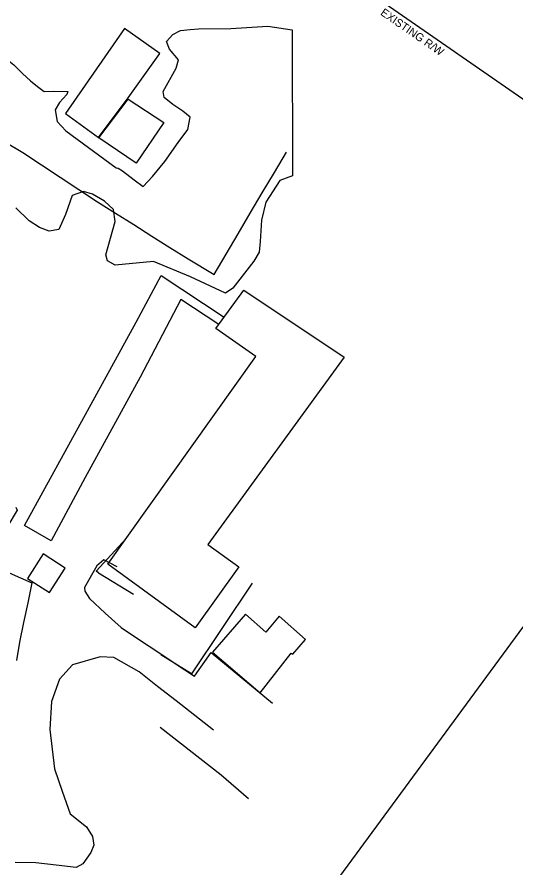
# Model space of a CAD drawing. Extents: x 2262665 to 2270527, y 505476 to 514960.
# Drawn here: x 2266517.9 to 2266717.5, y 511144.5 to 511484.8 of the extents above; entities that cross this region are included whole.
import ezdxf

# ---------------------------------------------------------------- set-up
doc = ezdxf.new("R2010")
doc.units = 0
for name, color, linetype in [('Exist Building', 7, 'Continuous'), ('Exist Building Metal Canopy', 7, 'Continuous'), ('Exist Other Culture Area Outline', 7, 'Continuous'), ('Exist Other Culture Fence Line', 7, 'Continuous'), ('Exist Other Culture Gate', 7, 'Continuous'), ('Exist Right of Way Line', 7, 'Continuous'), ('Exist Right of Way Line Text', 7, 'Continuous'), ('Exist Roads Soil', 7, 'Continuous'), ('Exist Vegetation Woods Line', 7, 'Continuous')]:
    doc.layers.add(name, color=color, linetype=linetype)

msp = doc.modelspace()

# ---------------------------------------------------------------- linework, layer by layer
at = {"layer": 'Exist Building'}
for points in [[(2266560.93, 511480.24), (2266537.28, 511446.18), (2266550.52, 511436.59), (2266562.38, 511452.46), (2266575.02, 511470.27)], [(2266606.61, 511264.93), (2266589.12, 511240.57), (2266554.22, 511265.94), (2266613.42, 511349.02), (2266597.45, 511360.18), (2266608.63, 511375.63), (2266648.76, 511348.83), (2266594.21, 511273.91)], [(2266609.31, 511246), (2266596.17, 511230.78), (2266615.18, 511214.55), (2266627.52, 511230.37), (2266628.22, 511229.93), (2266633.28, 511235.88), (2266622.82, 511245.18), (2266617.42, 511238.76)]]:
    msp.add_lwpolyline(points, close=True, dxfattribs=at)
at = {"layer": 'Exist Building Metal Canopy'}
msp.add_line((2266550.63, 511436.52), (2266562.42, 511452.01), dxfattribs=at)
msp.add_lwpolyline([(2266562.42, 511452.01), (2266576.62, 511442.59), (2266565.56, 511426.37), (2266550.63, 511436.52)], dxfattribs=at)
at = {"layer": 'Exist Other Culture Area Outline'}
msp.add_lwpolyline([(2266598.65, 511361.84), (2266583.47, 511371.86), (2266567.21, 511340.71), (2266545.23, 511300.7), (2266531.57, 511275.36), (2266520.88, 511281.5), (2266546.17, 511327.3), (2266565.58, 511362.73), (2266575.61, 511381.41), (2266600.8, 511364.81)], dxfattribs=at)
msp.add_lwpolyline([(2266537.24, 511264.35), (2266528.41, 511270.06), (2266522.11, 511260.3), (2266530.93, 511254.6)], close=True, dxfattribs=at)
at = {"layer": 'Exist Other Culture Fence Line'}
for points in [[(2266550.58, 511262.55), (2266549.59, 511263.13), (2266561.57, 511276.27)], [(2266550.58, 511262.55), (2266564.52, 511254.02)], [(2266612.03, 511258.39), (2266587.78, 511222.06)], [(2266575.2, 511200.76), (2266599.58, 511181.72), (2266610.52, 511172.23)]]:
    msp.add_lwpolyline(points, dxfattribs=at)
at = {"layer": 'Exist Other Culture Gate'}
msp.add_line((2266587.78, 511222.06), (2266575.51, 511229.67), dxfattribs=at)
at = {"layer": 'Exist Right of Way Line'}
for p in [(2266538.53, 511578.02), (2265436.99, 509495.4)]:
    msp.add_line(p, (2266823.18, 511380.77), dxfattribs=at)
at = {"layer": 'Exist Roads Soil'}
for points in [[(2266477.55, 511455.85), (2266484.74, 511451.58), (2266491.93, 511447.31), (2266499.12, 511443.03), (2266506.31, 511438.76), (2266513.26, 511434.71), (2266520.22, 511430.66), (2266527.69, 511425.73), (2266535.16, 511420.8), (2266542.64, 511415.87), (2266550.11, 511410.95), (2266557.36, 511406.37), (2266564.6, 511401.79), (2266571.85, 511397.21), (2266579.1, 511392.63), (2266586.35, 511388.05), (2266596.72, 511381.85), (2266601.55, 511390.01), (2266606.37, 511398.16), (2266611.2, 511406.32), (2266616.02, 511414.47), (2266620.85, 511422.63), (2266625.68, 511430.78)], [(2266517.5, 511288.72), (2266518.03, 511287.58), (2266513.9, 511280.59)], [(2266557.93, 511264.97), (2266552.59, 511267.69), (2266549.89, 511265.31), (2266544.87, 511256.7), (2266545.06, 511255.15), (2266546.9, 511252.27), (2266553.25, 511246.44), (2266559.61, 511240.6), (2266566.94, 511235.74), (2266574.27, 511230.89), (2266581.6, 511226.03), (2266588.93, 511221.17), (2266595.64, 511230.67), (2266601.76, 511225.59), (2266607.88, 511220.51), (2266614.01, 511215.43), (2266620.13, 511210.35)], [(2266514.75, 511262.54), (2266523.84, 511258.47), (2266522.2, 511250.57), (2266520.57, 511242.67), (2266518.94, 511234.77), (2266517.72, 511227.4)], [(2266596.48, 511199.59), (2266589.05, 511205.42), (2266581.61, 511211.26), (2266574.18, 511217.09), (2266566.74, 511222.93), (2266556.62, 511228.61), (2266551.13, 511228.9), (2266540.17, 511225.77), (2266534.97, 511219.92), (2266531.77, 511211.1), (2266531.09, 511199.9), (2266531.98, 511191.99), (2266532.86, 511184.09), (2266536.05, 511175.13), (2266539.24, 511166.18), (2266545.73, 511160.91), (2266548.06, 511157.02), (2266548.67, 511153.54), (2266547.46, 511150.65), (2266544.22, 511146.12), (2266541.64, 511144.67), (2266533.58, 511145.56), (2266525.52, 511146.46), (2266517.19, 511146.69)]]:
    msp.add_lwpolyline(points, dxfattribs=at)
at = {"layer": 'Exist Vegetation Woods Line'}
for points in [[(2266495.74, 511490.65), (2266496.69, 511484.03), (2266500.48, 511478.79), (2266505.52, 511474.86), (2266510.52, 511470.56), (2266516.59, 511465.71), (2266520.17, 511462.29), (2266523.28, 511459.37), (2266526.14, 511457.07), (2266528.73, 511455.02), (2266532.56, 511455.11), (2266538.27, 511455.1), (2266537.85, 511453.86), (2266534.92, 511450.61), (2266533.14, 511447.7), (2266534.05, 511443.03), (2266537.46, 511439.33), (2266557.64, 511424.56)], [(2266587.22, 511479.81), (2266590.56, 511480.05), (2266603.42, 511480.27), (2266618.3, 511481.19), (2266628, 511479.75), (2266628.12, 511421.24), (2266622.99, 511419.4), (2266617.44, 511410.76), (2266615.71, 511403.57), (2266615.13, 511395.06), (2266614.73, 511390.74), (2266612.66, 511387.18), (2266604.21, 511376.42), (2266601.32, 511374.36), (2266587.34, 511380.93), (2266572.56, 511387.09), (2266557.14, 511385.53), (2266554.09, 511387.3), (2266553.43, 511389.69), (2266557.24, 511403.07), (2266556.56, 511407.79), (2266552.98, 511411.21), (2266548.13, 511413.92), (2266544.48, 511415.02), (2266539.97, 511413.41), (2266537.38, 511405.85), (2266534.64, 511399.87), (2266530.74, 511399.19), (2266526.9, 511400.68), (2266522.8, 511403.32), (2266517.43, 511408.48)], [(2266557.64, 511424.56), (2266558.36, 511424.38), (2266560.12, 511423.33), (2266564.78, 511419.65), (2266568.44, 511417.1), (2266572.13, 511421.1), (2266577.04, 511427.04), (2266582.44, 511434.6), (2266586.25, 511439.79), (2266587.17, 511444.83), (2266584.27, 511447.12), (2266580.23, 511449.79), (2266576.72, 511452.7), (2266576.33, 511455.06), (2266581.52, 511464.4), (2266582.57, 511467.76), (2266578.92, 511471.94), (2266577.67, 511475.07), (2266580.21, 511477.85), (2266583.38, 511479.4), (2266587.22, 511479.81)]]:
    msp.add_lwpolyline(points, dxfattribs=at)

# ---------------------------------------------------------------- texts
at = {"layer": 'Exist Right of Way Line Text'}
msp.add_text('EXISTING R/W', height=3.2, rotation=325.2806, dxfattribs=at).set_placement((2266663.01, 511485.92))

doc.saveas('drawing.dxf')
